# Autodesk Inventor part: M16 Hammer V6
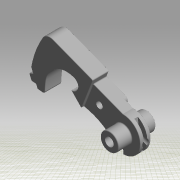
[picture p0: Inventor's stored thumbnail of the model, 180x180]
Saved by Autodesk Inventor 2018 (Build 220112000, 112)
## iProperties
Created: 2019-01
Part Number: M16 Hammer V6
Material: Generic
Document SubType Name: Modeling
Designer: johne
Appearance: Default
Sending System: Autodesk Inventor 2018
Preprocessor: ST-DEVELOPER v16.13
Title: D:\Downloads\AP9 Shit\M16 Hammer V6.stp
Author: johne
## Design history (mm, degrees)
feature "Solid2"
body "Solid1"
